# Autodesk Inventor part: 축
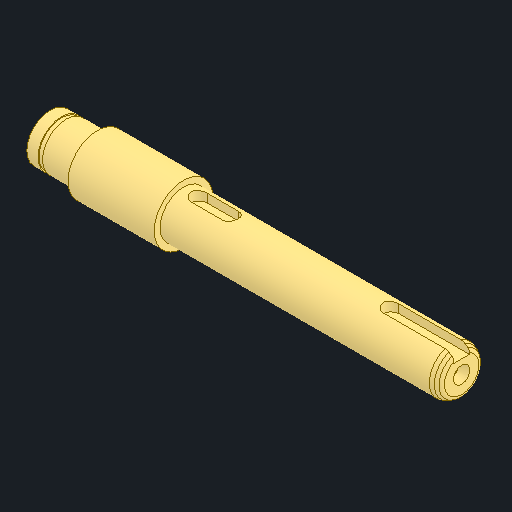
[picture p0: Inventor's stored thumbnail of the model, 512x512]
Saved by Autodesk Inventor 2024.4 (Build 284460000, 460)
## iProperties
Created: 2026-03
Part Number: 축
Material: 강철, 탄소
Document SubType Name: Modeling
Designer: user
Density: 7.85 g/cm^3
Appearance: 기본값
Author: jhkim
Sending System: Autodesk Inventor 2026
Preprocessor: ST-DEVELOPER v20.1
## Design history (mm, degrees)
feature "솔리드1"
node "솔리드2"
